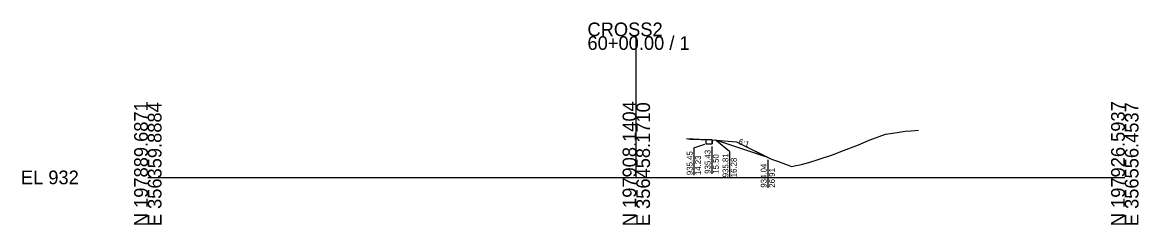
# Model space of a CAD drawing. Extents: x -26 to 203, y -10 to 14021.
# Drawn here: x -25.7 to 202.8, y 990.3 to 1031.8 of the extents above; entities that cross this region are included whole.
import ezdxf

# ---------------------------------------------------------------- set-up
doc = ezdxf.new("R2010")
doc.units = 0
for name, color, linetype in [('Default', 7, 'Continuous'), ('P_E_XS_Ground', 7, 'Continuous'), ('P_XS', 7, 'Continuous'), ('P_XS_EAR_CommonGrnd', 7, 'Continuous'), ('P_XS_Lane', 7, 'Continuous'), ('P_XS_Rock', 7, 'Continuous')]:
    doc.layers.add(name, color=color, linetype=linetype)

msp = doc.modelspace()

# ---------------------------------------------------------------- linework, layer by layer
at = {"layer": 'Default'}
for p, q in [((100, 1000), (100, 1028.94)), ((0, 1000), (100, 1000)), ((100, 1000), (200, 1000))]:
    msp.add_line(p, q, dxfattribs=at)
at = {"layer": 'P_E_XS_Ground'}
for p, q in [((110.28, 1007.95), (111.05, 1007.86)), ((111.05, 1007.86), (115.5, 1007.69)), ((147.68, 1007.65), (151, 1008.87)), ((151, 1008.87), (153.37, 1009.22)), ((153.37, 1009.22), (155.06, 1009.47)), ((155.06, 1009.47), (156.19, 1009.56)), ((156.19, 1009.56), (157.78, 1009.65)), ((115.5, 1007.69), (120.5, 1007.29)), ((120.5, 1007.29), (127.65, 1003.71)), ((142.39, 1005.53), (145.48, 1006.66)), ((145.48, 1006.66), (147.68, 1007.65)), ((127.65, 1003.71), (128.88, 1003.34)), ((128.88, 1003.34), (131.11, 1002.5)), ((135.33, 1003.05), (137.4, 1003.77)), ((137.4, 1003.77), (140.18, 1004.65)), ((140.18, 1004.65), (142.39, 1005.53)), ((131.11, 1002.5), (131.79, 1002.25)), ((131.79, 1002.25), (132.37, 1002.4)), ((132.37, 1002.4), (133.79, 1002.63)), ((133.79, 1002.63), (135.33, 1003.05))]:
    msp.add_line(p, q, dxfattribs=at)
at = {"layer": 'P_XS'}
for p, q in [((110.28, 1007.94), (114.28, 1007.78)), ((114.28, 1007.78), (115.5, 1007.69))]:
    msp.add_line(p, q, dxfattribs=at)
at = {"layer": 'P_XS_EAR_CommonGrnd'}
for points in [[(114.23, 1006.9), (115.5, 1006.85), (115.5, 1007.69), (114.23, 1007.74)], [(116.28, 1007.62), (120.5, 1007.29), (126.91, 1004.08)]]:
    msp.add_lwpolyline(points, close=True, dxfattribs=at)
at = {"layer": 'P_XS_Lane'}
for p, q in [((114.23, 1007.74), (114.23, 1006.9)), ((114.23, 1006.9), (115.5, 1006.85)), ((115.5, 1007.69), (115.5, 1006.85)), ((115.5, 1007.69), (116.28, 1007.62)), ((126.91, 1004.08), (116.28, 1007.62))]:
    msp.add_line(p, q, dxfattribs=at)
at = {"layer": 'P_XS_Rock'}
for p, q in [((111.78, 1006.07), (114, 1006.83)), ((111.78, 1006.07), (111.78, 1000.47)), ((115.44, 1006.33), (115.44, 1000.74)), ((119.1, 1005.31), (116.43, 1007.5)), ((119.1, 1005.31), (119.1, 1000.02)), ((126.92, 1003.58), (126.92, 997.89))]:
    msp.add_line(p, q, dxfattribs=at)

# ---------------------------------------------------------------- texts
at = {"layer": 'Default'}
for s, p in [('CROSS2', (90, 1028.94)), ('60+00.00 / 1', (90, 1026.14)), ('EL 932', (-26, 998.6))]:
    msp.add_text(s, height=2.8, dxfattribs=at).set_placement(p)
for s, p in [('N 197889.6871', (0, 990)), ('E 356359.8884', (2.8, 990)), ('N 197908.1404', (100, 990)), ('E 356458.1710', (102.8, 990)), ('N 197926.5937', (200, 990)), ('E 356556.4537', (202.8, 990))]:
    msp.add_text(s, height=2.8, rotation=90, dxfattribs=at).set_placement(p)
at = {"layer": 'P_XS_Rock'}
for s, rotation, p in [('6:1', 341.5651, (120.8, 1006.85)), ('935.43', 90, (115.19, 1000.74)), ('935.45', 90, (111.53, 1000.47)), ('14.23', 90, (113.23, 1000.47)), ('15.50', 90, (116.89, 1000.74)), ('935.81', 90, (118.85, 1000.02)), ('16.28', 90, (120.55, 1000.02)), ('934.04', 90, (126.67, 997.89)), ('26.91', 90, (128.37, 997.89))]:
    msp.add_text(s, height=1.2, rotation=rotation, dxfattribs=at).set_placement(p)

doc.saveas('drawing.dxf')
